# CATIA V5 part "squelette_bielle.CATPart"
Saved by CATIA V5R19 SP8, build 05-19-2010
Part number: squelette_bielle
Publications: "Droite.1", "Droite.2", "Droite.3", "Plan.1"
Bounding box of the stored display mesh (mm): x 83 to 83, y 30.629 to 319.01, z 29.559 to 64.516
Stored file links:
  G:\EU_thinkMotion\CFAO_2010\MMS_groupe3\MMS_groupe3\A reprendre\amenand\amenand\squelette_bielle.CATPart
  F:\thinkmotion CFAO v12.1\essuie_glace.CATProduct
  G:\EU_thinkMotion\CFAO_2010\MMS_groupe3\MMS_groupe3\A reprendre\amenand\amenand\squelette_bielle_manivelle.CATPart
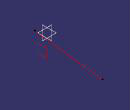
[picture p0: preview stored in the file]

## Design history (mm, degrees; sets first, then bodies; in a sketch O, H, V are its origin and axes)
Set1
  Plane1: linked copy from another document
  Point1 to Point3: linked copy from another document
Set2 "set géométrique.4"
  Line1: type PtPt, FirstPoint Point1, SecondPoint Point3
Body1 (main body)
